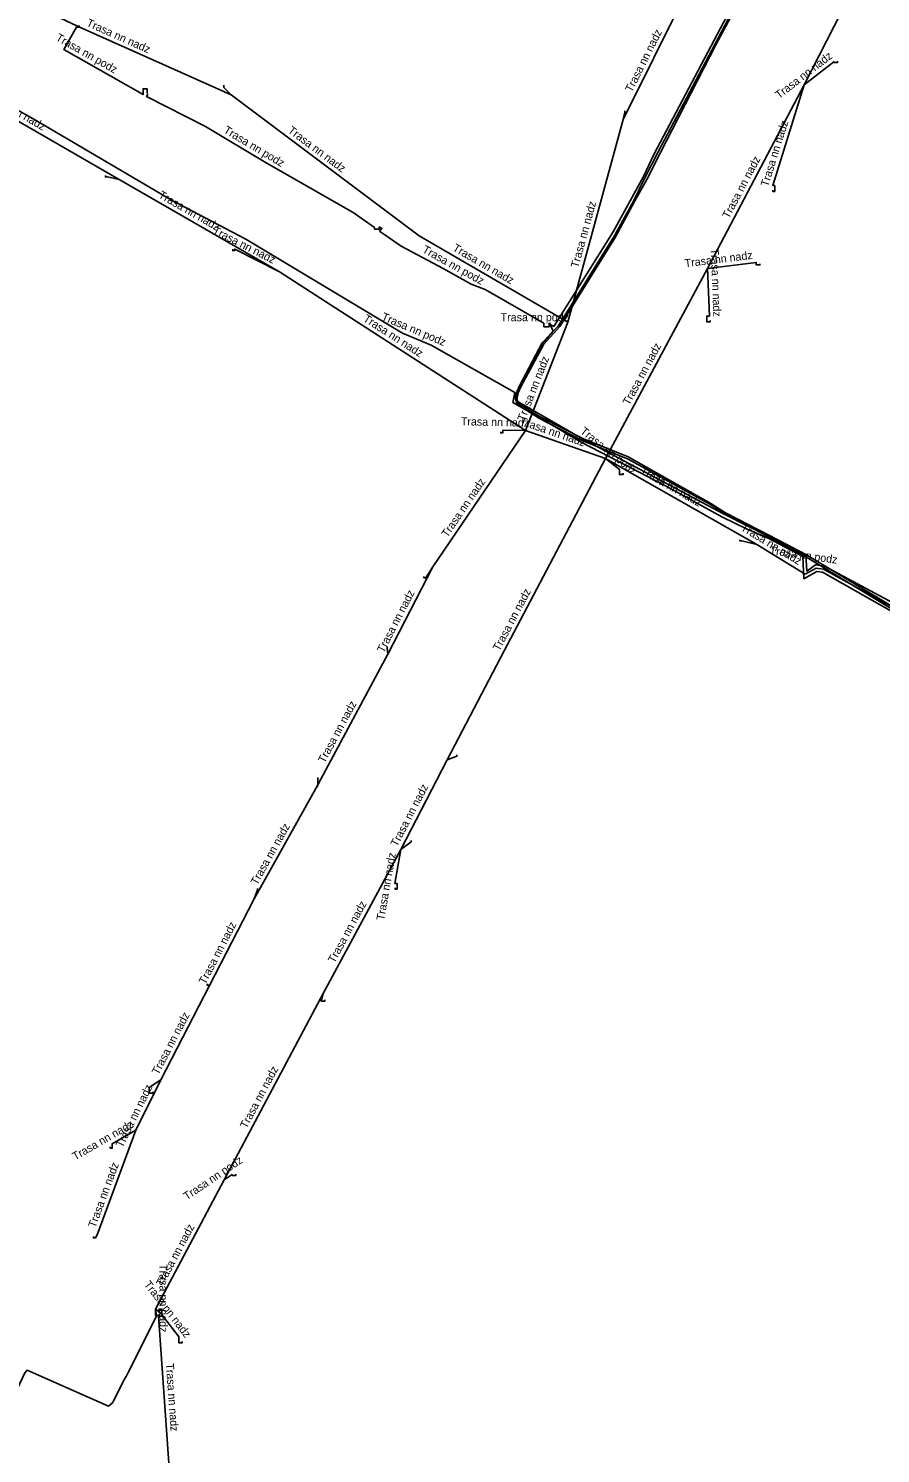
# Model space of a CAD drawing. Extents: x -742082 to -717476, y -1040737 to -1024597.
# Drawn here: x -736004.4 to -735897.9, y -1032747.5 to -1032569.4 of the extents above; entities that cross this region are included whole.
import ezdxf

# ---------------------------------------------------------------- set-up
doc = ezdxf.new("R2010")
doc.units = 0
for name, color, linetype in [('Level 13', 7, 'Continuous'), ('Level 14', 7, 'Continuous'), ('Level 15', 7, 'Continuous'), ('Level 20', 7, 'Continuous'), ('Level 25', 7, 'Continuous')]:
    doc.layers.add(name, color=color, linetype=linetype)

msp = doc.modelspace()

# ---------------------------------------------------------------- linework, layer by layer
at = {"layer": 'Level 13'}
for p, q in [((-735893.71, -1032549.48), (-735907.45, -1032576.44)), ((-735930.1, -1032580.8), (-735921.4, -1032563.3)), ((-735993.1, -1032588.3), (-736016.6, -1032574.7)), ((-735907.45, -1032576.44), (-735919.55, -1032599.41)), ((-735955.6, -1032595.3), (-735979.1, -1032577.7)), ((-735937.02, -1032606.12), (-735930.1, -1032580.8)), ((-735973.04, -1032599.81), (-735993.1, -1032588.3)), ((-735937.02, -1032606.12), (-735955.6, -1032595.3)), ((-735942.31, -1032619.67), (-735973.04, -1032599.81)), ((-735919.55, -1032599.41), (-735932.29, -1032623.14)), ((-735942.31, -1032619.67), (-735937.02, -1032606.12)), ((-735942.31, -1032619.67), (-735953.9, -1032636.7)), ((-735932.29, -1032623.14), (-735942.31, -1032619.67)), ((-735932.29, -1032623.14), (-735913.4, -1032633.9)), ((-735913.4, -1032633.9), (-735907.32, -1032637.61)), ((-735953.9, -1032636.7), (-735959.5, -1032647.6)), ((-735959.5, -1032647.6), (-735968.5, -1032664.4)), ((-735952.1, -1032660.8), (-735957.9, -1032672)), ((-735968.5, -1032664.4), (-735976.2, -1032678.2)), ((-735957.9, -1032672), (-735967.6, -1032690)), ((-735976.2, -1032678.2), (-735981.78, -1032689.02)), ((-735981.78, -1032689.02), (-735987.9, -1032700.8)), ((-735967.6, -1032690), (-735979.95, -1032713.32)), ((-735987.9, -1032700.8), (-735991, -1032707.1)), ((-735991, -1032707.1), (-735995.83, -1032720.19)), ((-735979.95, -1032713.32), (-735988.55, -1032729.46))]:
    msp.add_line(p, q, dxfattribs=at)
for points in [[(-735979.1, -1032577.7), (-735998.23, -1032569.17), (-736004.3, -1032566.3)], [(-735980, -1032576.5), (-735980, -1032576.78), (-735979.1, -1032577.7)], [(-735929.9, -1032579.7), (-735929.9, -1032579.86), (-735930.1, -1032580.8)], [(-735994.8, -1032587.8), (-735994.8, -1032587.96), (-735994.55, -1032587.96), (-735993.1, -1032588.3)], [(-735932.29, -1032623.14), (-735944.95, -1032647.2), (-735952.1, -1032660.8)], [(-735915.5, -1032633.3), (-735915.5, -1032633.46), (-735915.24, -1032633.46), (-735913.4, -1032633.9)], [(-735955, -1032637.9), (-735955, -1032638.06), (-735954.74, -1032638.06), (-735953.9, -1032636.7)], [(-735959.6, -1032646.7), (-735959.6, -1032646.86), (-735959.5, -1032647.6)], [(-735950.9, -1032660.2), (-735950.9, -1032660.36), (-735952.1, -1032660.8)], [(-735968.26, -1032663.02), (-735968.26, -1032664.01), (-735968.5, -1032664.4)], [(-735956.6, -1032670.9), (-735956.6, -1032671.06), (-735957.9, -1032672)], [(-735975.8, -1032676.9), (-735975.8, -1032677.05), (-735976.2, -1032678.2)], [(-735982.1, -1032688.8), (-735982.1, -1032688.96), (-735981.84, -1032688.96), (-735981.78, -1032689.02)], [(-735967.4, -1032690.8), (-735967.4, -1032690.96), (-735967.85, -1032690.96), (-735967.6, -1032690)], [(-735988.9, -1032702.3), (-735988.9, -1032702.46), (-735989.35, -1032702.46), (-735989.35, -1032701.75), (-735987.9, -1032700.8)], [(-735996.3, -1032720.4), (-735996.3, -1032720.56), (-735996.05, -1032720.56), (-735995.83, -1032720.19)], [(-735988.55, -1032729.46), (-735988.48, -1032729.55), (-735988.55, -1032729.55), (-735988.55, -1032730.26), (-735988.1, -1032730.26), (-735988.1, -1032730.1)], [(-735988.1, -1032729.99), (-735988.1, -1032729.45), (-735987.74, -1032729.45), (-735987.74, -1032730.36), (-735988.17, -1032730.36), (-735986.3, -1032757)]]:
    msp.add_lwpolyline(points, dxfattribs=at)
at = {"layer": 'Level 14'}
for points in [[(-735907.45, -1032576.44), (-735903.75, -1032573.57), (-735903.75, -1032573.66), (-735903.3, -1032573.66), (-735903.3, -1032573.5)], [(-735907.45, -1032576.44), (-735911.39, -1032589.05), (-735911.15, -1032589.05), (-735911.15, -1032589.76), (-735911.4, -1032589.76), (-735911.4, -1032589.6)], [(-735973.04, -1032599.81), (-735978.65, -1032596.98), (-735978.65, -1032597.16), (-735978.9, -1032597.16), (-735978.9, -1032597)], [(-735919.55, -1032599.41), (-735913.45, -1032598.64), (-735913.45, -1032598.96), (-735913, -1032598.96), (-735913, -1032598.8)], [(-735919.55, -1032599.41), (-735919.31, -1032605.35), (-735919.65, -1032605.35), (-735919.65, -1032606.06), (-735919.2, -1032606.06), (-735919.2, -1032605.9)], [(-735942.31, -1032619.67), (-735945.15, -1032619.61), (-735945.15, -1032619.96), (-735945.4, -1032619.96), (-735945.4, -1032619.8)], [(-735957.9, -1032672), (-735958.64, -1032676.25), (-735958.34, -1032676.25), (-735958.34, -1032676.96), (-735958.6, -1032676.96), (-735958.6, -1032676.8)], [(-735991, -1032707.1), (-735993.95, -1032708.8), (-735993.95, -1032709.36), (-735994.2, -1032709.36), (-735994.2, -1032709.2)], [(-735988.55, -1032729.46), (-735987.97, -1032729.89), (-735985.6, -1032732.95), (-735985.65, -1032732.95), (-735985.65, -1032733.66), (-735985.2, -1032733.66), (-735985.2, -1032733.5)]]:
    msp.add_lwpolyline(points, dxfattribs=at)
at = {"layer": 'Level 15'}
for points in [[(-735912.38, -1032558.84), (-735926.24, -1032585.16), (-735927.56, -1032587.91), (-735931.32, -1032594.83), (-735938.74, -1032606.66)], [(-735989.59, -1032577.47), (-735989.59, -1032576.93), (-735990.11, -1032576.93), (-735990.11, -1032577.67), (-735999.99, -1032572.04), (-735998.44, -1032569.25), (-735998.11, -1032569.25), (-735998.11, -1032569.04)], [(-736015.33, -1032574.27), (-736003.74, -1032580.74), (-735986.47, -1032590.9), (-735977.25, -1032595.74), (-735957.66, -1032607.48), (-735954.09, -1032608.99), (-735943.63, -1032614.92), (-735943.89, -1032616.14), (-735940.28, -1032618.19), (-735935.36, -1032621.09), (-735924.65, -1032626.63), (-735917.74, -1032630.42), (-735914.58, -1032632), (-735911.98, -1032633.12), (-735907.62, -1032635.41), (-735907.49, -1032638.17), (-735905.9, -1032637.26), (-735905.19, -1032637.36), (-735894.86, -1032643.18)], [(-735960.61, -1032594.18), (-735960.61, -1032594.49), (-735961.16, -1032594.49), (-735961.17, -1032594.29), (-735963.85, -1032592.42), (-735974.73, -1032586.19), (-735982.31, -1032581.65), (-735989.66, -1032577.91), (-735989.61, -1032577.78), (-735989.56, -1032577.78), (-735989.56, -1032577.58)], [(-735939.34, -1032606.19), (-735939.34, -1032606.69), (-735939.99, -1032606.69), (-735939.99, -1032606.25), (-735947.33, -1032602.01), (-735949.07, -1032601.36), (-735952.6, -1032599.39), (-735957.86, -1032596.6), (-735960.54, -1032594.73), (-735960.24, -1032594.39), (-735960.61, -1032594.18)], [(-735894.57, -1032642.14), (-735904.92, -1032636.59), (-735906.06, -1032636.43), (-735907.14, -1032637.22), (-735907.24, -1032635.17), (-735911.8, -1032632.76), (-735914.42, -1032631.64), (-735917.56, -1032630.06), (-735935.19, -1032620.69), (-735943.44, -1032615.94), (-735943.11, -1032614.38), (-735940.17, -1032608.76), (-735938.86, -1032607.24), (-735939.29, -1032606.19)], [(-735938.74, -1032606.66), (-735938.87, -1032606.58), (-735939.04, -1032606.49), (-735939.26, -1032606.49), (-735939.26, -1032606.19)], [(-735932.29, -1032623.14), (-735930.55, -1032624.52), (-735930.55, -1032625.16), (-735930.1, -1032625.16), (-735930.1, -1032625)], [(-735874.88, -1032665.94), (-735874.88, -1032666.38), (-735876.15, -1032666.39), (-735876.15, -1032665.17), (-735873.7, -1032663.33), (-735871.66, -1032662.46), (-735869.77, -1032661.16), (-735870.28, -1032658.55), (-735883.85, -1032649.6), (-735888.51, -1032646.84), (-735888.82, -1032646.89), (-735892.3, -1032644.85), (-735893.47, -1032644.24), (-735894.73, -1032642.65), (-735905.06, -1032636.97), (-735905.98, -1032636.84), (-735907.32, -1032637.61)], [(-735979.95, -1032713.32), (-735978.95, -1032712.64), (-735978.95, -1032712.76), (-735978.5, -1032712.76), (-735978.5, -1032712.6)], [(-735988.55, -1032729.46), (-735988.46, -1032729.96), (-735988.45, -1032730.43), (-735991.98, -1032737.38), (-735992.23, -1032737.87), (-735992.52, -1032738.35), (-735993.9, -1032741.15), (-735994.44, -1032741.59), (-736004.59, -1032737.11), (-736004.87, -1032737.43), (-736007.93, -1032743.94), (-736012.91, -1032753.1), (-736016.99, -1032756.02), (-736020.75, -1032755.53), (-736021.28, -1032755.77), (-736024.14, -1032760.7), (-736024.37, -1032761.13)]]:
    msp.add_lwpolyline(points, dxfattribs=at)
at = {"layer": 'Level 25'}
for points in [[(-735892.61, -1032644.31), (-735907.39, -1032635.36), (-735911.92, -1032632.92), (-735917.38, -1032630.04), (-735919.19, -1032628.9), (-735929.45, -1032623.24), (-735935.2, -1032620.91), (-735940.56, -1032618.16), (-735943.36, -1032616.36), (-735943.63, -1032615.41), (-735943.05, -1032614.06), (-735940.23, -1032608.7), (-735938.21, -1032606.6), (-735931.27, -1032595.43), (-735928.81, -1032590.99), (-735927.42, -1032588.14), (-735925.73, -1032584.83), (-735918.58, -1032571.32), (-735912.19, -1032559.12)], [(-735912.15, -1032559.53), (-735918.46, -1032571.38), (-735925.48, -1032585), (-735927.15, -1032588.27), (-735928.66, -1032591.01), (-735931.07, -1032595.51), (-735938.01, -1032606.67), (-735940, -1032608.86), (-735942.83, -1032614.12), (-735943.42, -1032615.39), (-735943.2, -1032616.27), (-735940.4, -1032617.97), (-735935.06, -1032620.69), (-735929.45, -1032622.95), (-735919.12, -1032628.76), (-735917.29, -1032629.92), (-735911.79, -1032632.77), (-735907.26, -1032635.14), (-735892.44, -1032644.08), (-735880.97, -1032651.09), (-735871.31, -1032657.08), (-735869.92, -1032658.36), (-735869.51, -1032661.56), (-735869.8, -1032662.72)]]:
    msp.add_lwpolyline(points, dxfattribs=at)

# ---------------------------------------------------------------- texts
at = {"layer": 'Level 20'}
for s, rotation, p in [('Trasa nn nadz', 335.9578, (-735997.27, -1032569.05)), ('Trasa nn podz', 330.3226, (-736001.1, -1032570.83)), ('Trasa nn nadz', 63.5661, (-735929, -1032577.46)), ('Trasa nn nadz', 37.7866, (-735910.6, -1032578.25)), ('Trasa nn nadz', 329.941, (-736010.04, -1032577.92)), ('Trasa nn podz', 329.1008, (-735980.13, -1032582.37)), ('Trasa nn nadz', 323.1691, (-735972.08, -1032582.33)), ('Trasa nn nadz', 72.646, (-735911.98, -1032589.25)), ('Trasa nn nadz', 62.22, (-735916.87, -1032593.25)), ('Trasa nn nadz', 330.1537, (-735988.27, -1032590.49)), ('Trasa nn nadz', 74.716, (-735935.7, -1032599.39)), ('Trasa nn nadz', 333.2049, (-735981.49, -1032594.98)), ('Trasa nn podz', 330.845, (-735955.28, -1032597.32)), ('Trasa nn nadz', 329.7789, (-735951.49, -1032597.11)), ('Trasa nn nadz', 7.1655, (-735922.34, -1032599.26)), ('Trasa nn nadz', 272.2852, (-735919.15, -1032596.91)), ('Trasa nn nadz', 327.1187, (-735962.68, -1032605.91)), ('Trasa nn podz', 337.075, (-735960.38, -1032605.79)), ('Trasa nn podz', 360, (-735945.41, -1032605.99)), ('Trasa nn nadz', 61.7782, (-735929.33, -1032616.58)), ('Trasa nn nadz', 68.6645, (-735942.42, -1032618.57)), ('Trasa nn nadz', 358.6699, (-735950.39, -1032618.99)), ('Trasa nn nadz', 340.9314, (-735943.08, -1032618.88)), ('Trasa nn podz', 321.4874, (-735935.54, -1032619.91)), ('Trasa nn nadz', 330.3284, (-735928.06, -1032624.97)), ('Trasa nn nadz', 55.7629, (-735952.06, -1032633.1)), ('Trasa nn nadz', 328.6128, (-735915.47, -1032632.05)), ('Trasa nn podz', 351.8792, (-735911.83, -1032635.1)), ('Trasa nn nadz', 62.2474, (-735945.56, -1032647.3)), ('Trasa nn nadz', 62.8076, (-735960.02, -1032647.51)), ('Trasa nn nadz', 61.8214, (-735967.41, -1032661.31)), ('Trasa nn nadz', 62.6223, (-735958.34, -1032671.75)), ('Trasa nn nadz', 60.8397, (-735975.85, -1032676.55)), ('Trasa nn nadz', 80.1343, (-735959.96, -1032680.93)), ('Trasa nn nadz', 61.6803, (-735966.17, -1032686.3)), ('Trasa nn nadz', 62.7317, (-735982.31, -1032688.97)), ('Trasa nn nadz', 62.5357, (-735988.18, -1032700.26)), ('Trasa nn nadz', 62.0965, (-735977.16, -1032706.98)), ('Trasa nn nadz', 63.7999, (-735992.67, -1032709.37)), ('Trasa nn nadz', 29.9312, (-735998.59, -1032710.9)), ('Trasa nn podz', 34.2173, (-735984.63, -1032715.89)), ('Trasa nn nadz', 69.7611, (-735996.06, -1032719.37)), ('Trasa nn nadz', 61.9528, (-735987.65, -1032726.7)), ('Trasa nn nadz', 270, (-735988.05, -1032723.83)), ('Trasa nn nadz', 307.7637, (-735990.04, -1032726.4)), ('Trasa nn nadz', 274.0104, (-735987.25, -1032736.26))]:
    msp.add_text(s, height=1, rotation=rotation, dxfattribs=at).set_placement(p)

doc.saveas('drawing.dxf')
